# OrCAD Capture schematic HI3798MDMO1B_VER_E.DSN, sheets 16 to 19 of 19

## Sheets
16 SHEET16: size Custom
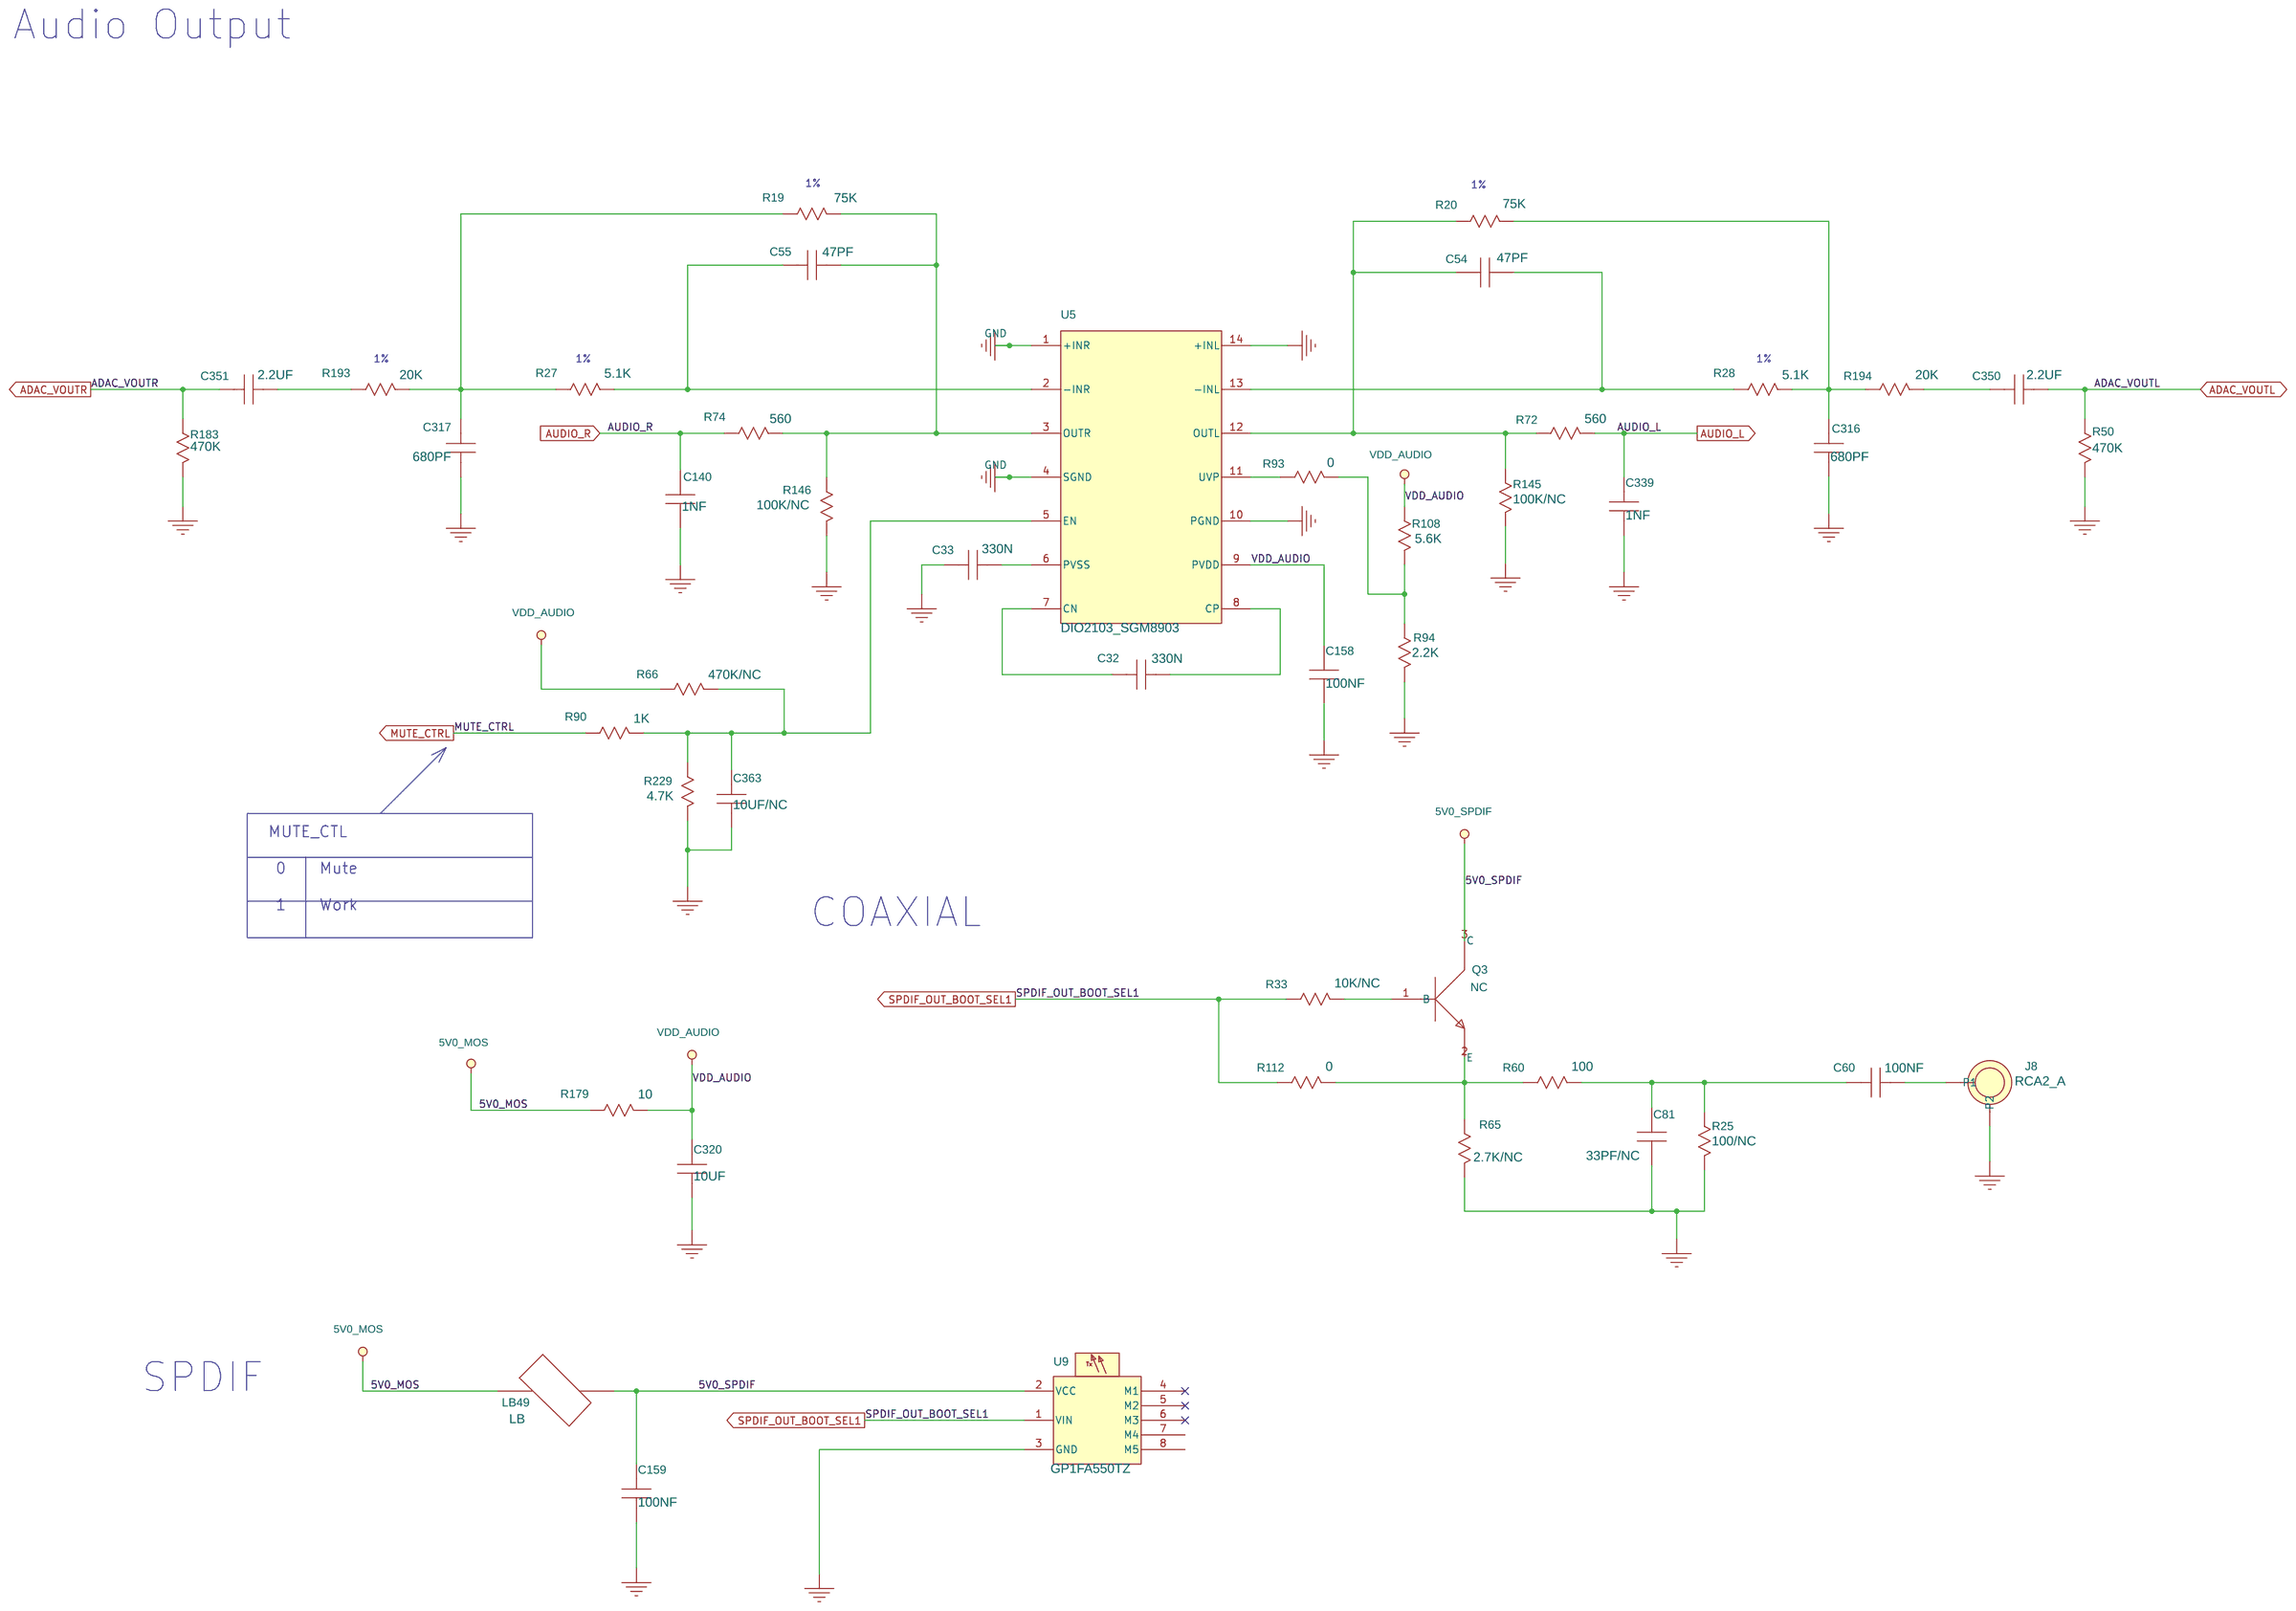
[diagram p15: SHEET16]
17 SHEET17: size Custom
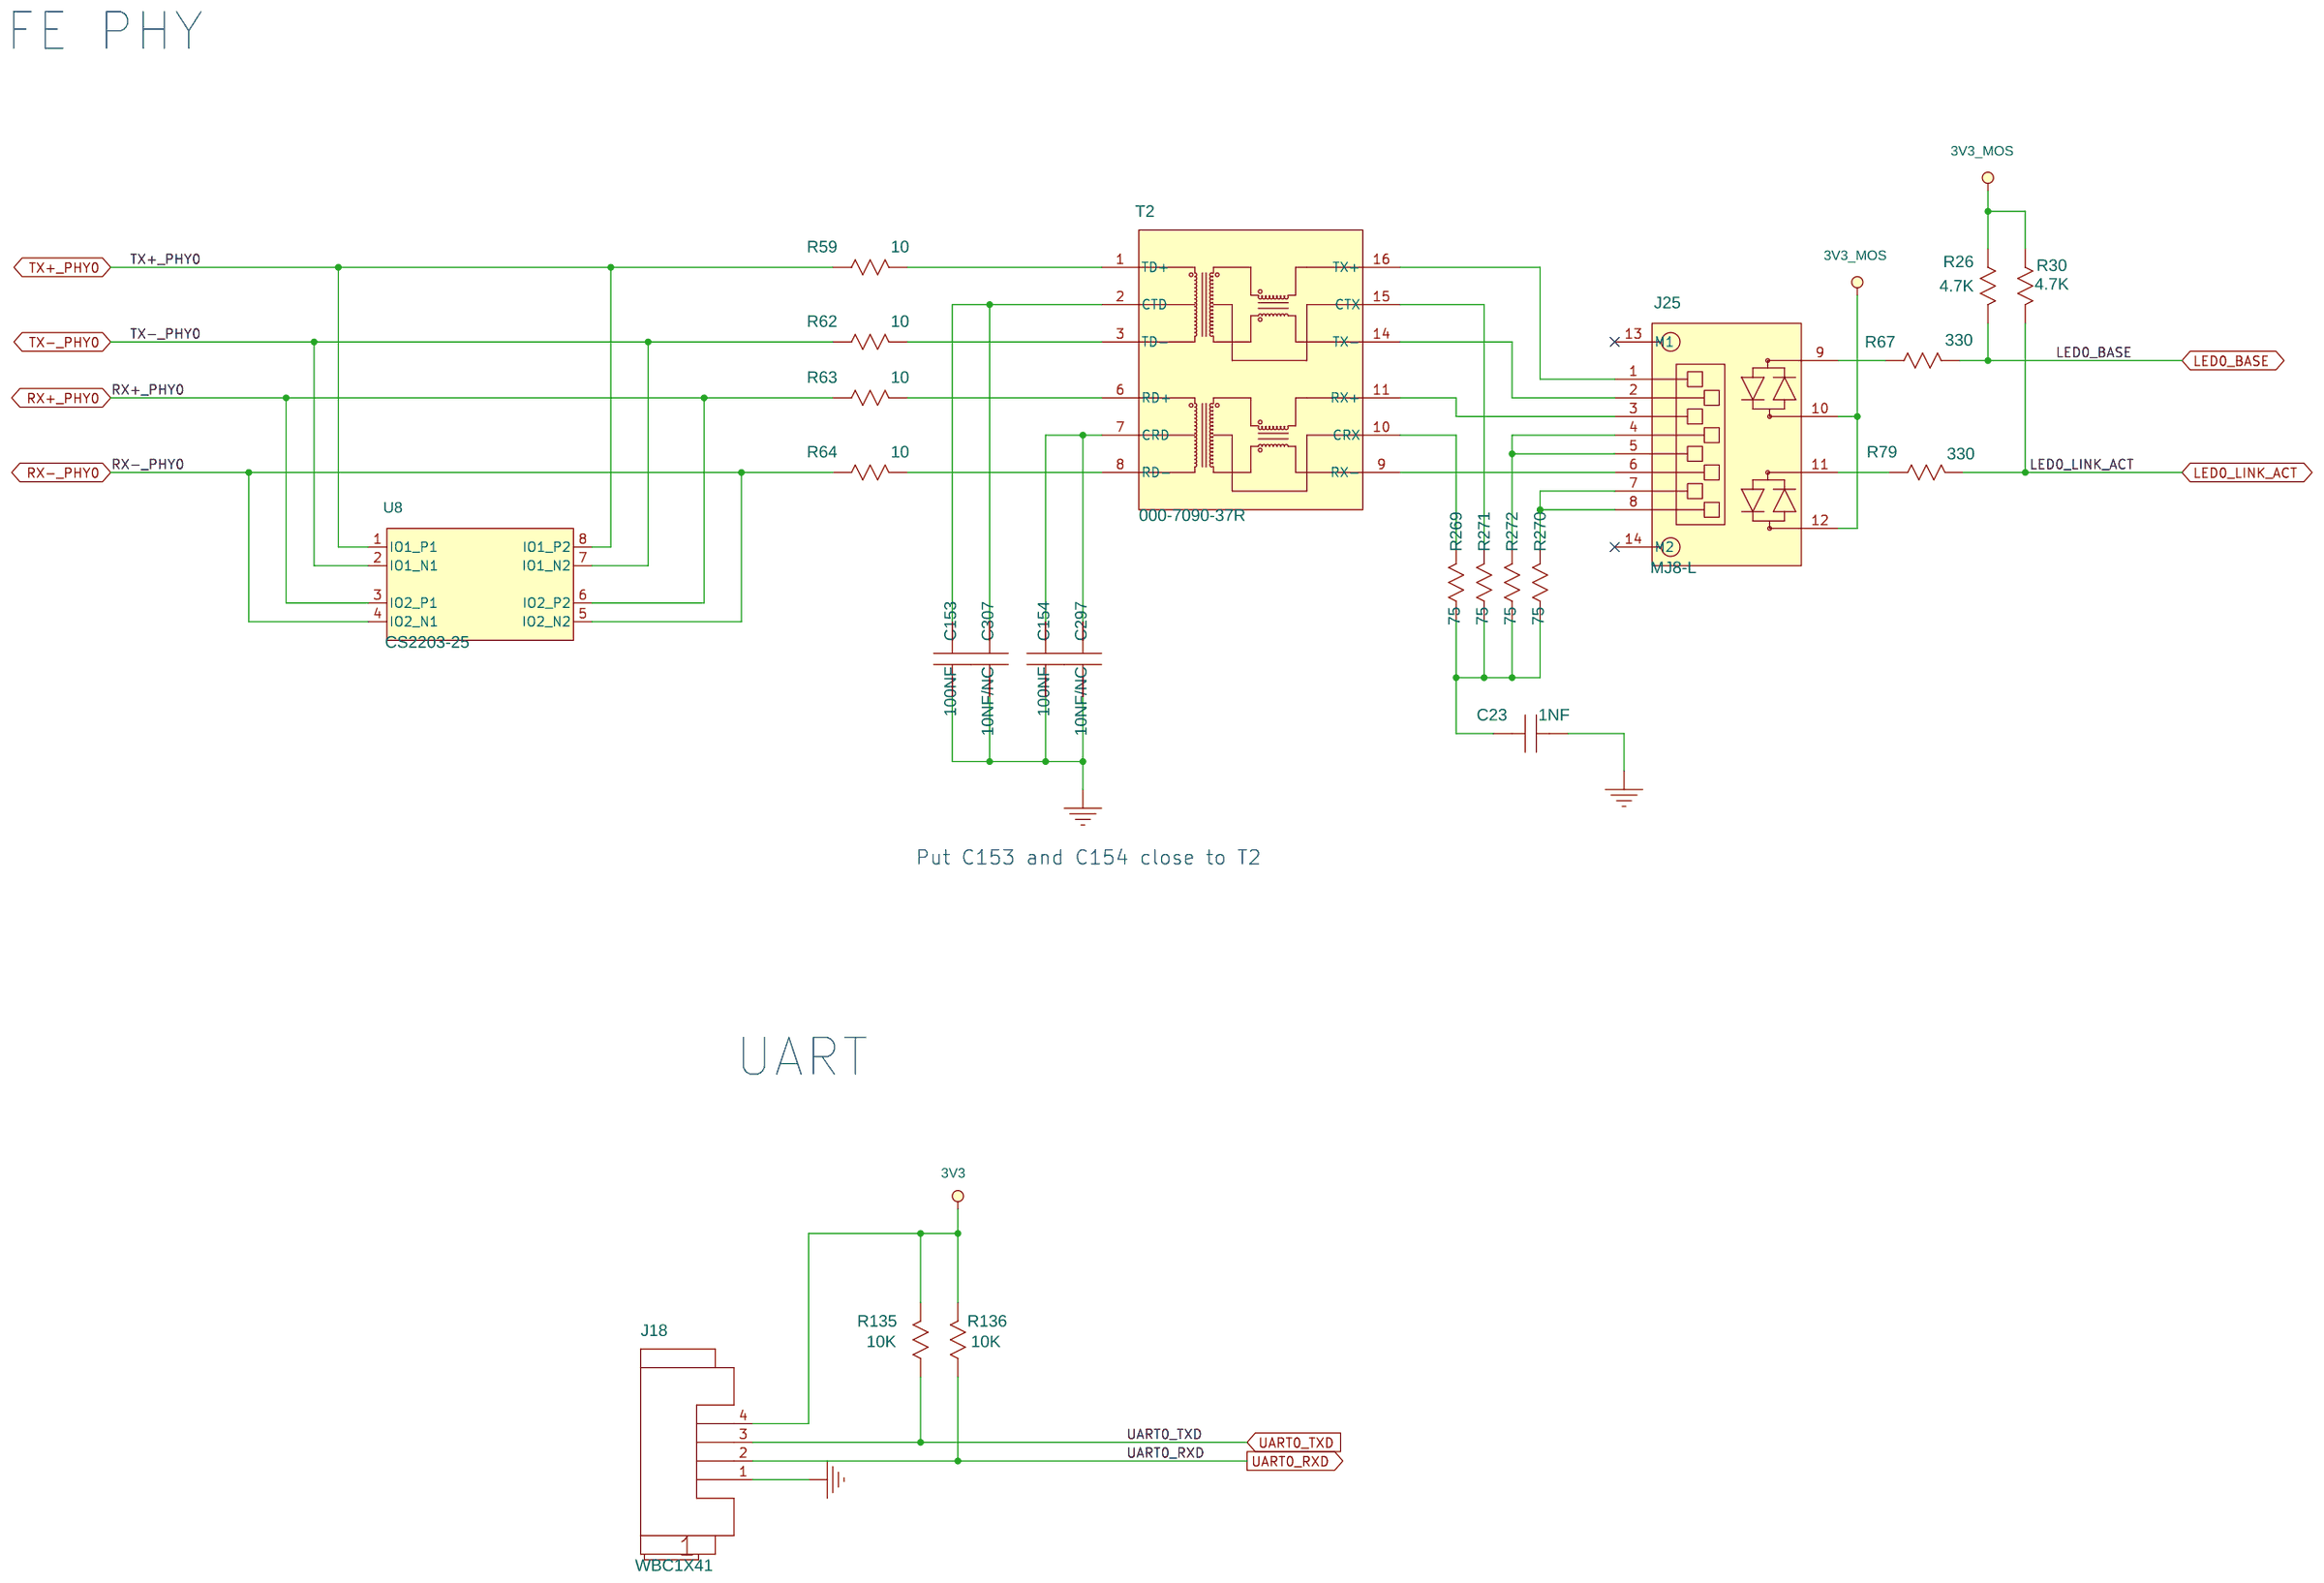
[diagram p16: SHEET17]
18 SHEET18: size A
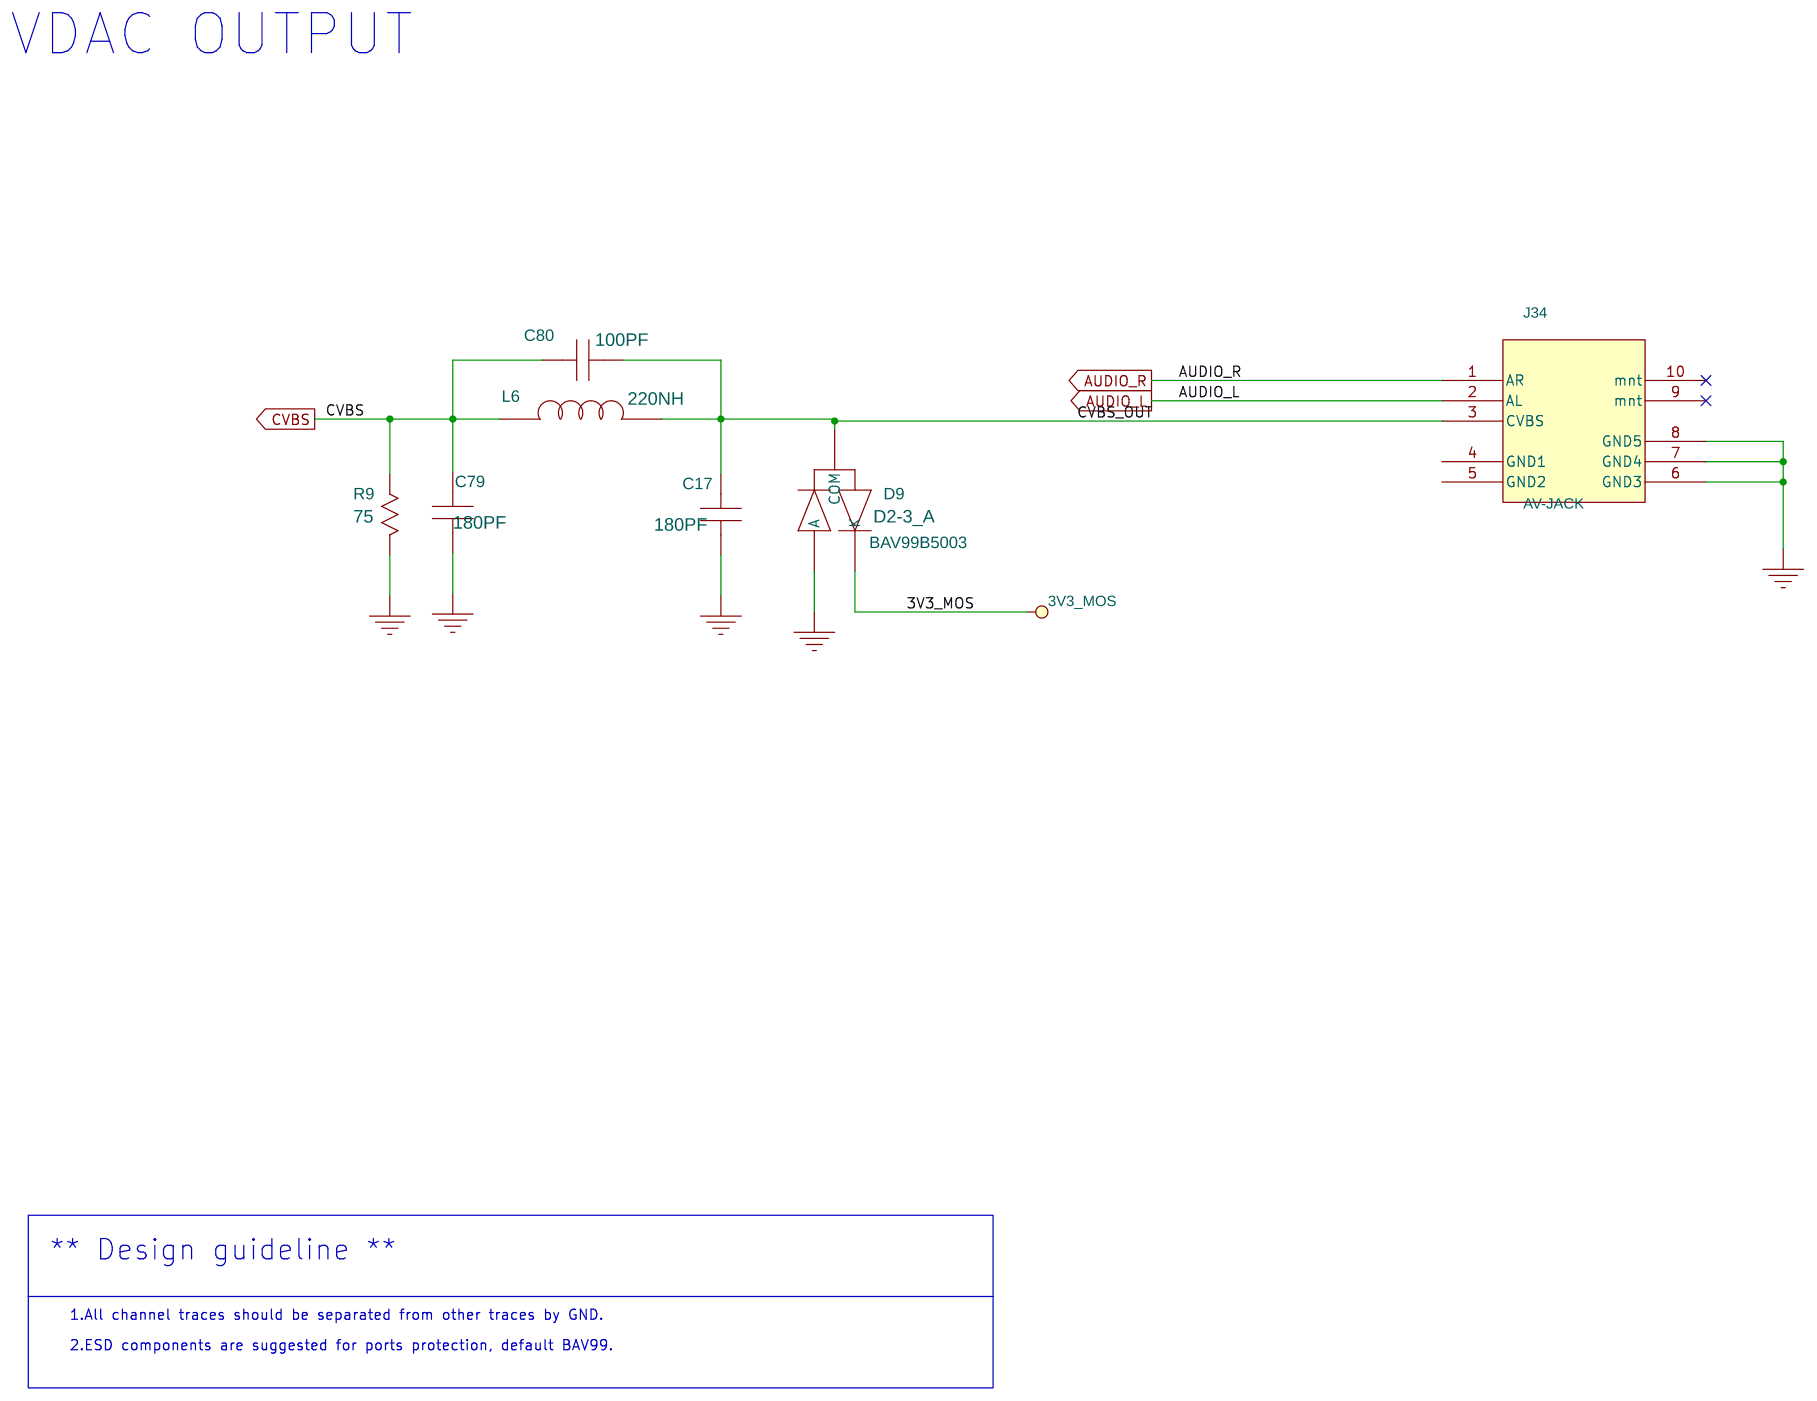
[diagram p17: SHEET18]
19 SHEET19: size Custom
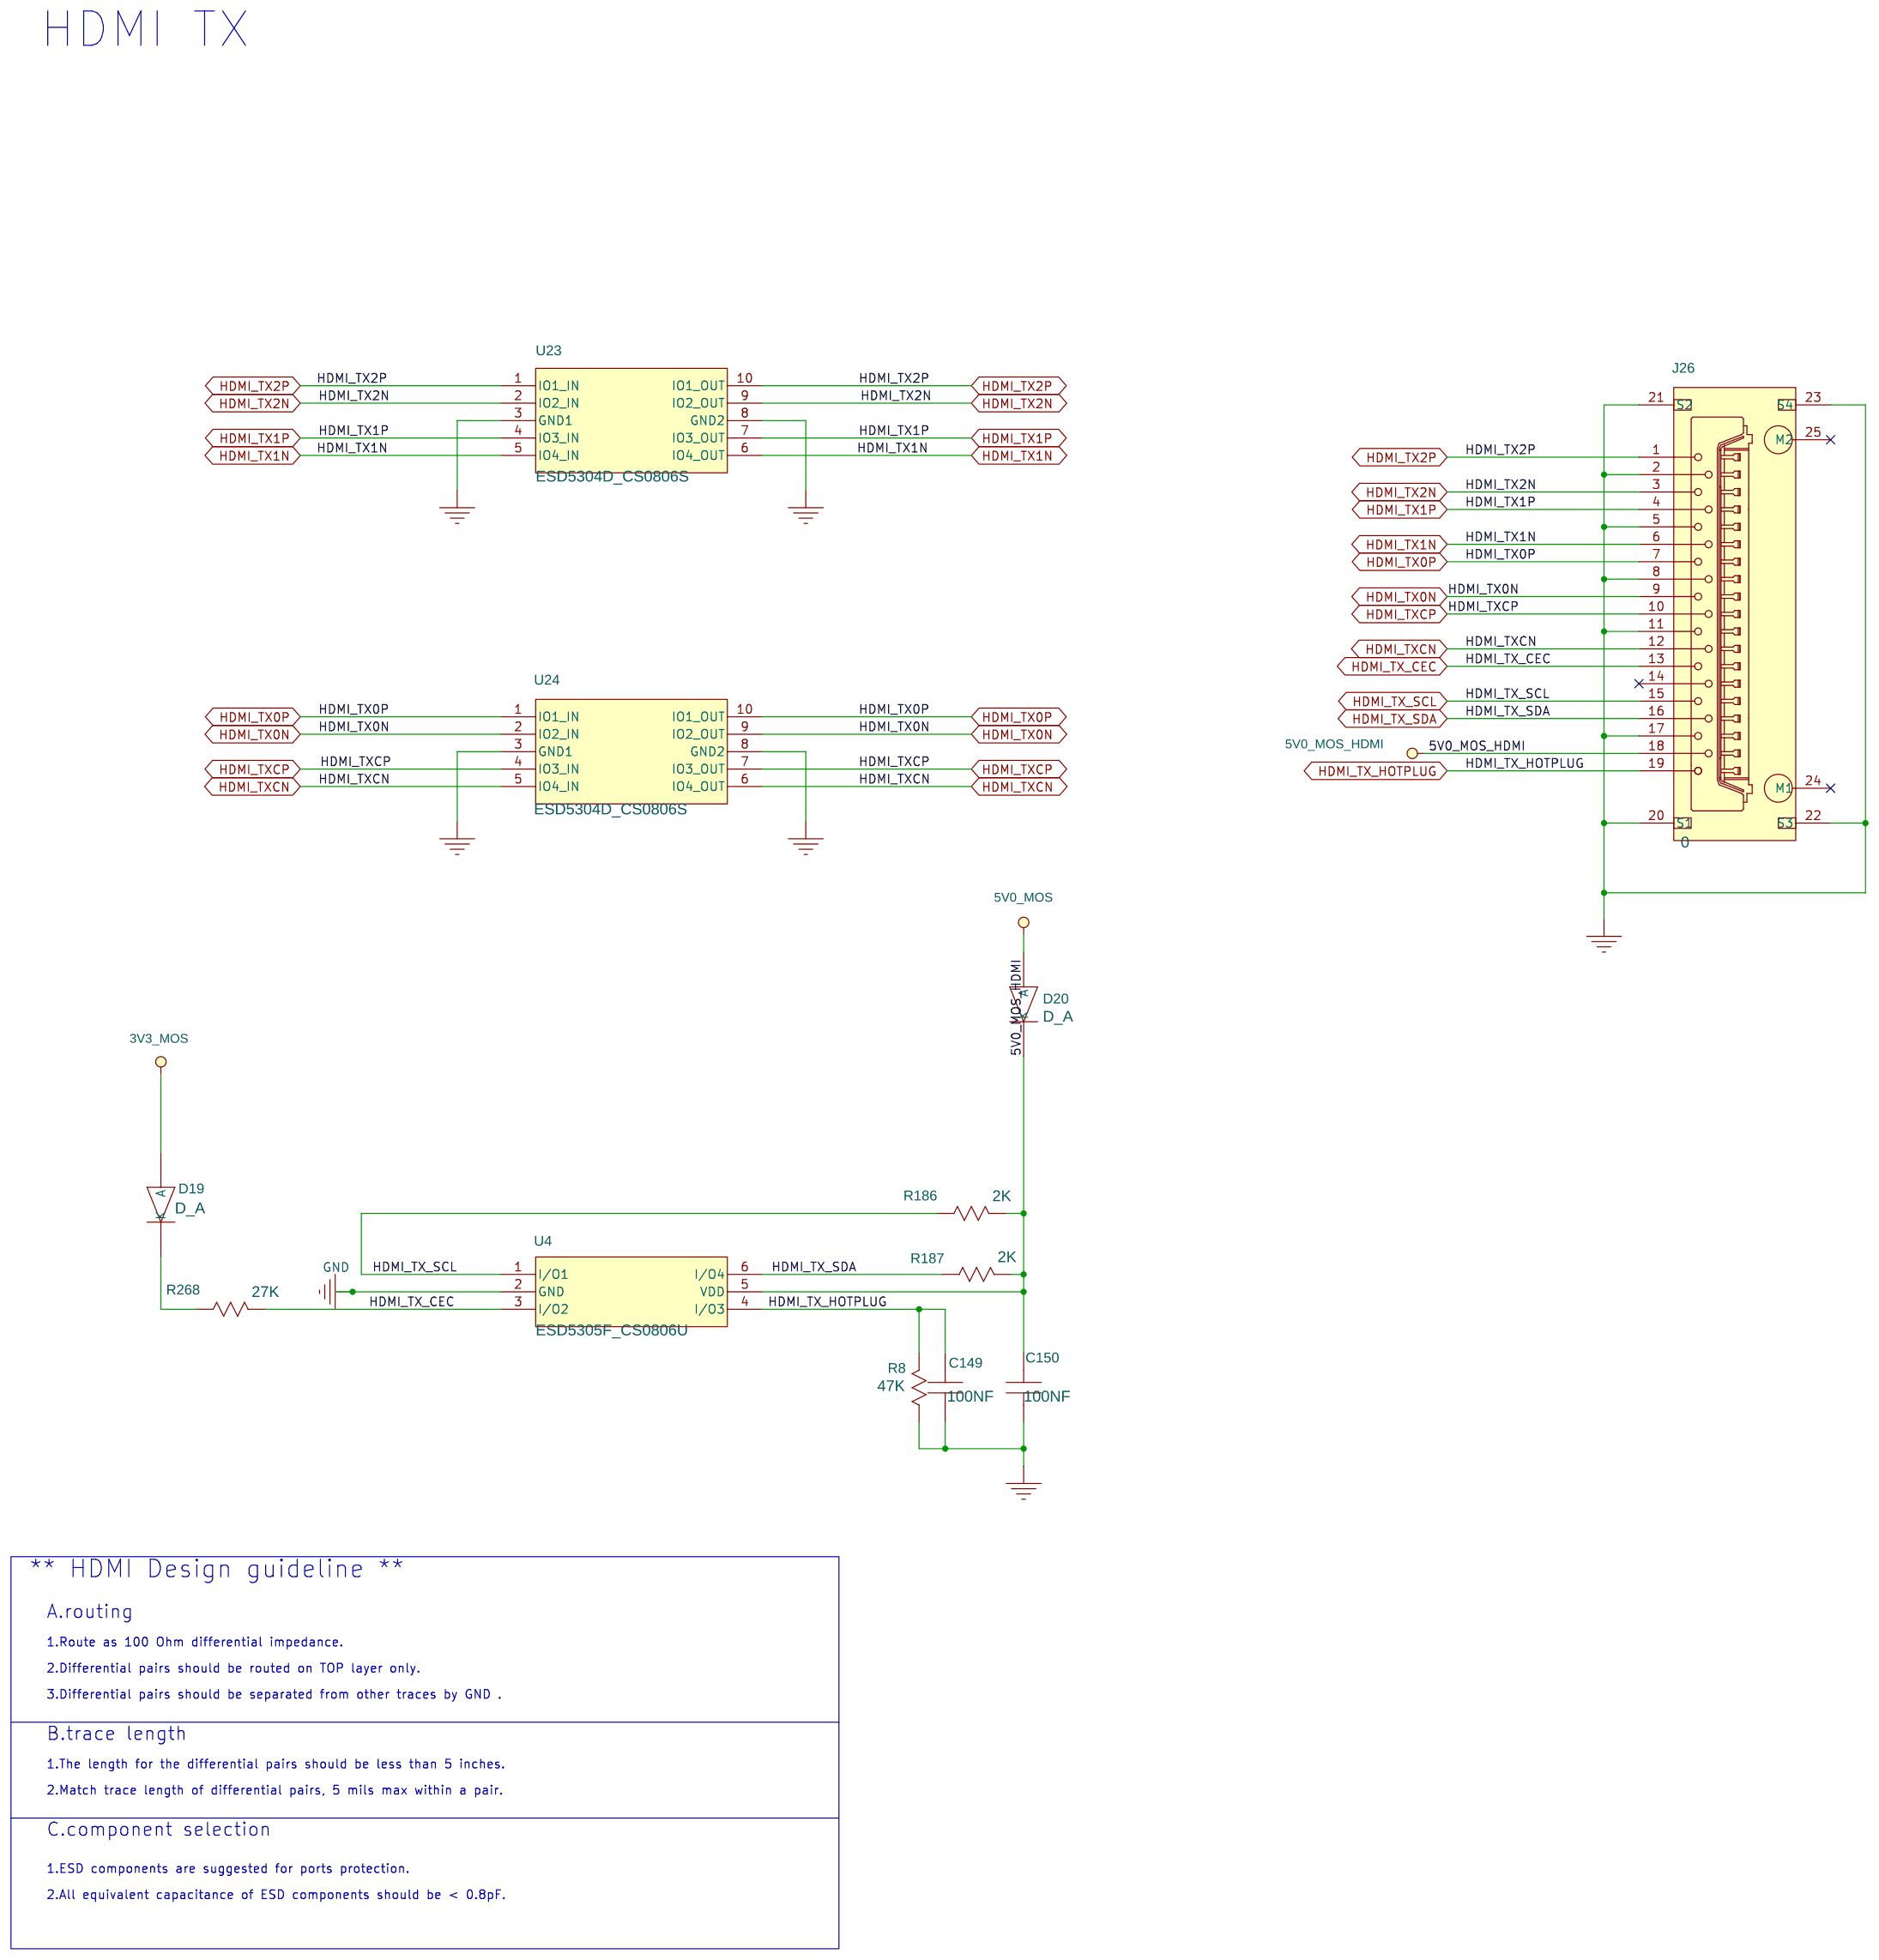
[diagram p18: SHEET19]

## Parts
sheet SHEET16
C32  330N  [HSC0402]
C33  330N  [HSC0402]
C54  47PF  [SC0402]
C55  47PF  [SC0402]
C60  100NF  [SC0402]
C81  33PF/NC  [SC0402]
C140  1NF  [SC0402]
C158  100NF  [SC0402]
C159  100NF  [SC0402]
C316  680PF  [SC0402]
C317  680PF  [SC0402]
C320  10UF  [SC0603]
C339  1NF  [SC0402]
C350  2.2UF  [SC0603]
C351  2.2UF  [SC0603]
C363  10UF/NC  [SC0603]
J8  RCA2_A  [VAF2]
LB49  LB  [SL0805]
Q3  NC  [SOT23]
R19  75K  [SR0603]
R20  75K  [SR0603]
R25  100/NC  [SR0402]
R27  5.1K  [SR0603]
R28  5.1K  [SR0603]
R33  10K/NC  [SR0402]
R50  470K  [SR0402]
R60  100  [SR0402]
R65  2.7K/NC  [SR0603]
R66  470K/NC  [SR0402]
R72  560  [HSR0402]
R74  560  [HSR0402]
R90  1K  [SR0402]
R93  0  [SR0402]
R94  2.2K  [SR0402]
R108  5.6K  [SR0402]
R112  0  [SR0402]
R145  100K/NC  [SR0402]
R146  100K/NC  [SR0402]
R179  10  [SR0603]
R183  470K  [SR0402]
R193  20K  [SR0402]
R194  20K  [SR0402]
R229  4.7K  [SR0402]
U5  DIO2103_SGM8903  [SGM8903]
U9  GP1FA550TZ  [LASER3-1214D]
sheet SHEET17
C23  1NF  [SC1206]
C153  100NF  [SC0402]
C154  100NF  [SC0402]
C297  10NF/NC  [SC0402]
C307  10NF/NC  [SC0402]
J18  WBC1X41  [WBC0104-49T]
J25  MJ8-L  [MJ8-RLY]
R26  4.7K  [SR0402]
R30  4.7K  [SR0402]
R59  10  [SR0402]
R62  10  [SR0402]
R63  10  [SR0402]
R64  10  [SR0402]
R67  330  [SR0402]
R79  330  [SR0402]
R135  10K  [SR0402]
R136  10K  [SR0402]
R269  75  [SR0805]
R270  75  [SR0805]
R271  75  [SR0805]
R272  75  [SR0805]
T2  000-7090-37R  [STFM16-50-285]
U8  CS2203-25  [RN8-0402]
sheet SHEET18
C17  180PF  [SC0402]
C79  180PF  [SC0402]
C80  100PF  [SC0402]
D9  D2-3_A  [SOT23]
J34  AV-JACK  [AV3-8-5-1]
L6  220NH  [SL0402]
R9  75  [SR0402]
sheet SHEET19
C149  100NF  [SC0402]
C150  100NF  [SC0402]
D19  D_A  [HSOD323A]
D20  D_A  [HSOD323A]
J26  0  [WBC0119-20R-A]
R8  47K  [SR0402]
R186  2K  [SR0402]
R187  2K  [SR0402]
R268  27K  [SR0402]
U4  ESD5305F_CS0806U  [SOT23A-6L]
U23  ESD5304D_CS0806S  [DFN2510P10E]
U24  ESD5304D_CS0806S  [DFN2510P10E]

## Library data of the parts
C32 C33 = C: %195%%232%%202%%246%: SMD陶瓷电容-6.3V-330NF-+/-10%-X5R-0402-终端专用; %208%%161%%192%%224%%195%%251%%179%%198%: SMD陶瓷电容; CODE: 8070953; COMPONENT_HIGH_MAX: 0.55MM; DEVICE: C1005X5R0J334K
C54 C55 = C: %182%%238%%182%%168%%185%%164%%215%%247%%181%%231%%209%%185%(V): 50; %195%%232%%202%%246%: SMD陶瓷电容-50V-0.047NF-+/-5%-NP0-0402; %208%%161%%192%%224%%195%%251%%179%%198%: SMD陶瓷电容; CODE: 8070549; COMPONENT_HIGH_MAX: 0.55MM; DEVICE: C0402C470J5GAC_7867
C60 C153 C154 C158 C159 = C: %182%%238%%182%%168%%185%%164%%215%%247%%181%%231%%209%%185%(V): 16; %195%%232%%202%%246%: SMD陶瓷电容-16V-100NF-±10%-X7R-0402; %208%%161%%192%%224%%195%%251%%179%%198%: SMD陶瓷电容; CODE: 8070614; COMPONENT_HIGH_MAX: 0.6MM; DEVICE: RMEMK105BJ104KV_FR
C81 = C: %182%%238%%182%%168%%185%%164%%215%%247%%181%%231%%209%%185%(V): 50; %195%%232%%202%%246%: SMD陶瓷电容-50V-0.033NF-+/-5%-NP0-0402-供电专用-08070547拆分-供电专用; %208%%161%%192%%224%%195%%251%%179%%198%: SMD陶瓷电容; CODE: 8070872; COMPONENT_HIGH_MAX: 0.55MM; DEVICE: C1005C0G1H330JT000F
C140 C339 = C: %182%%238%%182%%168%%185%%164%%215%%247%%181%%231%%209%%185%(V): 50; %195%%232%%202%%246%: SMD陶瓷电容-50V-1NF-+/-10%-X7R-0402-BT; %208%%161%%192%%224%%195%%251%%179%%198%: SMD陶瓷电容; CODE: 8070531; COMPONENT_HIGH_MAX: 0.55MM; DEVICE: 04025C102KAT2A
C316 C317 = C: %182%%238%%182%%168%%185%%164%%215%%247%%181%%231%%209%%185%(V): 50; %195%%232%%202%%246%: SMD陶瓷电容-50V-0.68NF-+/-5%-NP0-0402-供电专用-供电专用; %208%%161%%192%%224%%195%%251%%179%%198%: SMD陶瓷电容; CODE: 8070853; COMPONENT_HIGH_MAX: 0.55MM; DEVICE: C0402C681J5GAC7867
C320 C363 = C: %182%%238%%182%%168%%185%%164%%215%%247%%181%%231%%209%%185%(V): 6.3; %195%%232%%202%%246%: SMD陶瓷电容-6.3V-10000NF-+/-20%-X5R-0603-BT,TS16949; %208%%161%%192%%224%%195%%251%%179%%198%: SMD陶瓷电容; CODE: 8070649; COMPONENT_HIGH_MAX: 0.9MM; DEVICE: C1608X5R0J106MT0A0E
C350 C351 = C: %182%%238%%182%%168%%185%%164%%215%%247%%181%%231%%209%%185%(V): 10; %195%%232%%202%%246%: SMD陶瓷电容-10V-2200NF-+/-10%-X5R-0603; %208%%161%%192%%224%%195%%251%%179%%198%: SMD陶瓷电容; CODE: 8070573; COMPONENT_HIGH_MAX: 0.9MM; DEVICE: GRM188R61A225KE34D
J8 = RCA2_A: %195%%232%%202%%246%: 音视频连接器-RCA莲花插座-2PIN-弯母-PCB焊接型-红色; CODE: 14160120; COMPONENT_HIGH_MAX: 13.5MM; DEVICE: SCP624UNS2
LB49 = LB_v2: %195%%232%%202%%246%: EMI磁珠-220OHM-0.05OHM-2A-0805; %208%%161%%192%%224%%195%%251%%179%%198%: EMI磁珠; CODE: 10070012; COMPONENT_HIGH_MAX: 1.05MM; DEVICE: MGLB2012_220T_LF
Q3 = NPN-BEC: %195%%232%%202%%246%: 三极管-NPN-45V-100MA-225MW-200MV@100MA-SOT-23-180@2MA; %208%%161%%192%%224%%195%%251%%179%%198%: 三极管; CODE: 15050206; COMPONENT_HIGH_MAX: 1.26MM; DEVICE: BC847AE6327
R19 R20 = R: %182%%238%%182%%168%%185%%166%%194%%202%(W): 0.1; %195%%232%%202%%246%: 片式厚膜电阻器-0.1W-75000OHM-+/-1% -0603; %208%%161%%192%%224%%195%%251%%179%%198%: 片式厚膜电阻器; %215%%232%%214%%181%%212%%202%%208%%237%%198%%171%%178%%238%: +/-1%; CODE: 7091238; COMPONENT_HIGH_MAX: 0.55MM; DEVICE: RK73H1JTTD7502F
R25 R33 R60 R65 R112 = R: %195%%232%%202%%246%: 片式厚膜电阻器-0.0625W-100OHM-±5%-0402; CODE: 7090807; COMPONENT_HIGH_MAX: 0.4MM; DEVICE: RC0402JR_07100R
R27 R28 = R: %182%%238%%182%%168%%185%%166%%194%%202%(W): 0.1; %195%%232%%202%%246%: 片式厚膜电阻器-0.1W-5100OHM-+/-1%-0603; %208%%161%%192%%224%%195%%251%%179%%198%: 片式厚膜电阻器; %215%%232%%214%%181%%212%%202%%208%%237%%198%%171%%178%%238%: +/-1%; CODE: 7091295; COMPONENT_HIGH_MAX: 0.55MM; DEVICE: RC0603FR_075K1L
R50 R183 = R: %182%%238%%182%%168%%185%%166%%194%%202%(W): 0.06; %195%%232%%202%%246%: 片式厚膜电阻器-0.0625W-470000OHM-±1%-0402; %208%%161%%192%%224%%195%%251%%179%%198%: 片式厚膜电阻器; %215%%232%%214%%181%%212%%202%%208%%237%%198%%171%%178%%238%: ±1%; CODE: 7090855; COMPONENT_HIGH_MAX: 0.4MM; DEVICE: RK73H1ETTP4703F
R66 = R: %182%%238%%182%%168%%185%%166%%194%%202%(W): 0.06; %195%%232%%202%%246%: 片式厚膜电阻器-0.0625W-470000OHM-+/-1%-0402; %208%%161%%192%%224%%195%%251%%179%%198%: 片式厚膜电阻器; %215%%232%%214%%181%%212%%202%%208%%237%%198%%171%%178%%238%: +/-1%; CODE: 7090855; COMPONENT_HIGH_MAX: 0.4MM; DEVICE: RK73H1ETTP4703F
R72 R74 = R: %195%%232%%202%%246%: 片式厚膜电阻器-0.0625W-560OHM-+/-5%-0402-终端专用-终端专用; %208%%161%%192%%224%%195%%251%%179%%198%: 片式厚膜电阻器; CODE: 7091285; COMPONENT_HIGH_MAX: 0.4MM; DEVICE: RC0402JR_07560RL
R90 = R: %182%%238%%182%%168%%185%%166%%194%%202%(W): 0.06; %195%%232%%202%%246%: 片式厚膜电阻器-0.0625W-1000OHM-±5%-0402; %208%%161%%192%%224%%195%%251%%179%%198%: 片式厚膜电阻器; %215%%232%%214%%181%%212%%202%%208%%237%%198%%171%%178%%238%: ±5%; CODE: 7090809; COMPONENT_HIGH_MAX: 0.4MM; DEVICE: RC0402JR_071KL
R8 R93 = R: %182%%238%%182%%168%%185%%166%%194%%202%(W): 0.06; %195%%232%%202%%246%: 片式厚膜电阻器-0.0625W-47000OHM-+/-5%-0402-ELOM; %208%%161%%192%%224%%195%%251%%179%%198%: 片式厚膜电阻器; %215%%232%%214%%181%%212%%202%%208%%237%%198%%171%%178%%238%: +/-5%; CODE: 7090819; DEVICE: RC0402JR_0747K
R94 = R: %182%%238%%182%%168%%185%%166%%194%%202%(W): 0.06; %195%%232%%202%%246%: 片式厚膜电阻器-0.0625W-2200OHM-+/-1%-0402--供电专用-07090810-供电专用; %208%%161%%192%%224%%195%%251%%179%%198%: 片式厚膜电阻器; %215%%232%%214%%181%%212%%202%%208%%237%%198%%171%%178%%238%: +/-1%; CODE: 7091537; COMPONENT_HIGH_MAX: 0.4MM; DEVICE: RC0402FR_072K2L2
R108 = R: %182%%238%%182%%168%%185%%166%%194%%202%(W): 0.06; %195%%232%%202%%246%: 片式厚膜电阻器-0.0625W-5600OHM-+/-1%-0402-BT; %208%%161%%192%%224%%195%%251%%179%%198%: 片式厚膜电阻器; %215%%232%%214%%181%%212%%202%%208%%237%%198%%171%%178%%238%: +/-1%; CODE: 7091275; COMPONENT_HIGH_MAX: 0.4MM; DEVICE: RK73H1ETTP5601F
R145 R146 = R: %182%%238%%182%%168%%185%%166%%194%%202%(W): 0.06; %195%%232%%202%%246%: 片式厚膜电阻器-0.0625W-100000OHM-+/-5%-0402-BT; %208%%161%%192%%224%%195%%251%%179%%198%: 片式厚膜电阻器; %215%%232%%214%%181%%212%%202%%208%%237%%198%%171%%178%%238%: +/-5%; CODE: 7090831; COMPONENT_HIGH_MAX: 0.4MM; DEVICE: RK73B1ELTP104J
R179 = R: %182%%238%%182%%168%%185%%166%%194%%202%(W): 0.1; %195%%232%%202%%246%: 片式厚膜电阻器-0.1W-10OHM-+/-5%-0603-TS16949; %208%%161%%192%%224%%195%%251%%179%%198%: 片式厚膜电阻器; %215%%232%%214%%181%%212%%202%%208%%237%%198%%171%%178%%238%: +/-5%; CODE: 7090264; COMPONENT_HIGH_MAX: 0.55MM; DEVICE: RC0603JR_0710R
R193 R194 = R: %182%%238%%182%%168%%185%%166%%194%%202%(W): 0.06; %195%%232%%202%%246%: 片式厚膜电阻器-0.0625W-20000OHM-+/-1%-0402-TS16949; %208%%161%%192%%224%%195%%251%%179%%198%: 片式厚膜电阻器; %215%%232%%214%%181%%212%%202%%208%%237%%198%%171%%178%%238%: +/-1%; CODE: 7091374; COMPONENT_HIGH_MAX: 0.4MM; DEVICE: RC_02W2002FT
R229 = R: %182%%238%%182%%168%%185%%166%%194%%202%(W): 0.06; %195%%232%%202%%246%: 片式厚膜电阻器-0.0625W-4700OHM-+/-5%-0402-BT; %208%%161%%192%%224%%195%%251%%179%%198%: 片式厚膜电阻器; %215%%232%%214%%181%%212%%202%%208%%237%%198%%171%%178%%238%: +/-5%; CODE: 7090793; COMPONENT_HIGH_MAX: 0.4MM; DEVICE: RK73B1ELTP472J
U5 = SGM8903
U9 = GP1FA550TZ_1: %195%%232%%202%%246%: 光电器件-数字音频光纤接头-660NM; %208%%161%%192%%224%%195%%251%%179%%198%: 光电器件; CODE: 15020122; COMPONENT_HIGH_MAX: 19.1MM; DEVICE: GP1FAV50TK0F
C23 = C: %182%%238%%182%%168%%185%%164%%215%%247%%181%%231%%209%%185%(V): 2000; %195%%232%%202%%246%: SMD陶瓷电容-2000V-1NF-+/-20%-X7R-1206; %208%%161%%192%%224%%195%%251%%179%%198%: SMD陶瓷电容; CODE: 8070439; COMPONENT_HIGH_MAX: 1.52MM; DEVICE: 1206GC102MAT1A
C297 C307 = C: %182%%238%%182%%168%%185%%164%%215%%247%%181%%231%%209%%185%(V): 16; %195%%232%%202%%246%: SMD陶瓷电容-16V-10NF-+/-10%-X7R-0402-BT,TS16949; %208%%161%%192%%224%%195%%251%%179%%198%: SMD陶瓷电容; CODE: 8070449; COMPONENT_HIGH_MAX: 0.55MM; DEVICE: GRM155R71C103KA01D
J18 = WBC1X41: %195%%232%%202%%246%: 普通插座-4PIN-单排-直式-1.25MM-2MM-THT-1A; %208%%161%%192%%224%%195%%251%%179%%198%: 普通插座; CODE: 14100167; COMPONENT_HIGH_MAX: 4.2MM; DEVICE: SDW12501_4A_HW
J25 = MJ8-L: %195%%232%%202%%246%: 网口连接器-单排-单端口-8PIN-8BIT-非屏蔽-模型插座/侧面插入型-引脚长2.54MM-带固定脚/带灯; %208%%161%%192%%224%%195%%251%%179%%198%: 网口连接器; COMPONENT_HIGH_MAX: 13.2MM; DEVICE: 406533_1
R26 R30 = R: %182%%238%%182%%168%%185%%166%%194%%202%(W): 0.06; %195%%232%%202%%246%: 片式厚膜电阻器-0.0625W-4700OHM-+/-5%-0402; %208%%161%%192%%224%%195%%251%%179%%198%: 片式厚膜电阻器; %215%%232%%214%%181%%212%%202%%208%%237%%198%%171%%178%%238%: +/-5%; CODE: 7090793; COMPONENT_HIGH_MAX: 0.4MM; DEVICE: RK73B1ELTP472J
R59 R62-R64 R67 R79 = R: %182%%238%%182%%168%%185%%166%%194%%202%(W): 0.06; %195%%232%%202%%246%: 片式厚膜电阻器-0.0625W-330OHM-+/-1%-0402-BT; %208%%161%%192%%224%%195%%251%%179%%198%: 片式厚膜电阻器; %215%%232%%214%%181%%212%%202%%208%%237%%198%%171%%178%%238%: +/-1%; CODE: 7091333; COMPONENT_HIGH_MAX: 0.4MM; DEVICE: RC_02W3300FT
R135 R136 = R: %182%%238%%182%%168%%185%%166%%194%%202%(W): 0.06; %195%%232%%202%%246%: 片式厚膜电阻器-0.0625W-10000OHM-±5%-0402; %208%%161%%192%%224%%195%%251%%179%%198%: 片式厚膜电阻器; %215%%232%%214%%181%%212%%202%%208%%237%%198%%171%%178%%238%: ±5%; CODE: 7090815; COMPONENT_HIGH_MAX: 0.4MM; DEVICE: RC_02W103JT
R269-R272 = R: %182%%238%%182%%168%%185%%166%%194%%202%(W): 0.13; %195%%232%%202%%246%: 片式厚膜电阻器-0.125W-75OHM-±1%-0805; %208%%161%%192%%224%%195%%251%%179%%198%: 片式厚膜电阻器; %215%%232%%214%%181%%212%%202%%208%%237%%198%%171%%178%%238%: ±1%; CODE: 7090362; DEVICE: RC0805FR_0775R
T2 = 000-7090-37R: %195%%232%%202%%246%: LAN变压器-1CT:1CT-0.35MH-0UH-1路-2变压器-100BASE-T接口模块-SMT; %208%%161%%192%%224%%195%%251%%179%%198%: LAN变压器; CODE: 9050085; COMPONENT_HIGH_MAX: 6.2MM; DEVICE: H1102T
U8 = CS2203-25_1
C17 C79 = C: %182%%238%%182%%168%%185%%164%%215%%247%%181%%231%%209%%185%(V): 50; %195%%232%%202%%246%: SMD陶瓷电容-50V-0.18NF-+/-5%-NPO-0402; %208%%161%%192%%224%%195%%251%%179%%198%: SMD陶瓷电容; CODE: 8070637; COMPONENT_HIGH_MAX: 0.55MM; DEVICE: CC0402JRNPO9BB181
C80 = C: %182%%238%%182%%168%%185%%164%%215%%247%%181%%231%%209%%185%(V): 50; %195%%232%%202%%246%: SMD陶瓷电容-50V-0.1NF-±5%-NPO-0402; %208%%161%%192%%224%%195%%251%%179%%198%: SMD陶瓷电容; CODE: 8070450; COMPONENT_HIGH_MAX: 0.55MM; DEVICE: 04025A101JAT2A
D9 = D2-3_A: %195%%232%%202%%246%: 开关二极管-70V-200MA-1.25V-6NS-串联-SOT-23-2 FIT; %208%%161%%192%%224%%195%%251%%179%%198%: 开关二极管; CODE: 15010042; COMPONENT_HIGH_MAX: 1.26MM; DEVICE: BAV99B5003
J34 = AV-JACK1_0
L6 = L: %195%%232%%202%%246%: 贴片电感器-0.22UH-+/-5%-3.77OHM-0.3A-0402; %208%%161%%192%%224%%195%%251%%179%%198%: 贴片电感器; CODE: 10031264; COMPONENT_HIGH_MAX: 0.55MM; DEVICE: LGHK1005R22J_T
R9 = R: %182%%238%%182%%168%%185%%166%%194%%202%(W): 0.06; %195%%232%%202%%246%: 片式厚膜电阻器-0.0625W-75OHM-+/-1%-0402; %208%%161%%192%%224%%195%%251%%179%%198%: 片式厚膜电阻器; %215%%232%%214%%181%%212%%202%%208%%237%%198%%171%%178%%238%: +/-1%; CODE: 7091321; COMPONENT_HIGH_MAX: 0.4MM; DEVICE: RC_02W750FT
C149 C150 = C: %182%%238%%182%%168%%185%%164%%215%%247%%181%%231%%209%%185%(V): 16; %195%%232%%202%%246%: SMD陶瓷电容-16V-100NF-+/-10%-X7R-0402-BT; %208%%161%%192%%224%%195%%251%%179%%198%: SMD陶瓷电容; CODE: 8070614; COMPONENT_HIGH_MAX: 0.6MM; DEVICE: RMEMK105BJ104KV_FR
D19 D20 = D_A: %195%%232%%202%%246%: 肖特基二极管-10V-3A-0.24V-SOD323-BT; %208%%161%%192%%224%%195%%251%%179%%198%: 肖特基二极管; CODE: 15010252; COMPONENT_HIGH_MAX: 1.1MM; DEVICE: BAT60BE6327
J26 = WBC1X19S4M2: %195%%232%%202%%246%: IO连接器-HDMI 母座-19PIN-弯式-SMT带DIP脚-终端专用; %208%%161%%192%%224%%195%%251%%179%%198%: IO连接器; CODE: 14240146; COMPONENT_HIGH_MAX: 6.38MM; DEVICE: 1827059_3
R186 R187 = R: %182%%238%%182%%168%%185%%166%%194%%202%(W): 0.06; %195%%232%%202%%246%: 片式厚膜电阻器-0.0625W-2000OHM-+/-1%-0402-BT; %208%%161%%192%%224%%195%%251%%179%%198%: 片式厚膜电阻器; %215%%232%%214%%181%%212%%202%%208%%237%%198%%171%%178%%238%: +/-1%; CODE: 7091354; COMPONENT_HIGH_MAX: 0.4MM; DEVICE: RC_02W2001FT
R268 = R: %182%%238%%182%%168%%185%%166%%194%%202%(W): 0.06; %195%%232%%202%%246%: 片式厚膜电阻器-0.0625W-27000OHM-+/-5%-0402; %208%%161%%192%%224%%195%%251%%179%%198%: 片式厚膜电阻器; %215%%232%%214%%181%%212%%202%%208%%237%%198%%171%%178%%238%: +/-5%; CODE: 7090852; COMPONENT_HIGH_MAX: 0.4MM; DEVICE: RK73B1ETTP273J
U4 = CS0806U
U23 = CS0806S: #: 3
U24 = CS0806S

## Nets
3V3: J18.4 R135.1(A) R136.2(B) ; also on sheet 4 5 6 9 15
3V3_MOS: D9.2(K) D19.2(A) J25.10 J25.12 R26.1(A) R30.1(A) ; also on sheet 5 6 7 8 9 13 14 15
5V0_MOS: D20.2(A) LB49.1 R179.1(A) ; also on sheet 5 14
5V0_MOS_HDMI: C150.1(A) D20.1(K) J26.18 R186.2(B) R187.2(B) U4.5(VDD)
5V0_SPDIF: C159.1(A) LB49.2 Q3.3(C) U9.2(VCC)
GND: C17.2(B) C23.2(B) C33.1(A) C79.2(B) C81.2(B) C140.2(B) C149.2(B) C150.2(B) C153.2(B) C154.2(B) C158.2(B) C159.2(B) C297.2(B) C307.2(B) C316.2(B) C317.2(B) C320.2(B) C339.2(B) C363.2(B) D9.1(A) J8.2(P2) J18.1 J26.2 J26.5 J26.8 J26.11 J26.17 J26.20(S1) J26.21(S2) J26.22(S3) J26.23(S4) J34.6(GND3) J34.7(GND4) J34.8(GND5) R8.1(A) R9.2(B) R25.2(B) R50.2(B) R65.2(B) R94.2(B) R145.2(B) R146.2(B) R183.2(B) R229.2(B) U4.2(GND) U5.1(+INR) U5.4(SGND) U5.10(PGND) U5.14(+INL) U9.3(GND) U23.3(GND1) U23.8(GND2) U24.3(GND1) U24.8(GND2) ; also on sheet 3 4 5 6 7 8 9 10 11 12 13 14 15
VDD_AUDIO: C158.1(A) C320.1(A) R66.2(B) R108.1(A) R179.2(B) U5.9(PVDD)
ADAC_VOUTL: C350.2(B) R50.1(A) ; also on sheet 7
ADAC_VOUTR: C351.1(A) R183.1(A) ; also on sheet 7
AUDIO_L: C339.1(A) J34.2(AL) R72.2(B)
AUDIO_R: C140.1(A) J34.1(AR) R74.1(A)
CVBS: C79.1(A) C80.1(A) L6.1(A) R9.1(A) ; also on sheet 7
CVBS_OUT: C17.1(A) C80.2(B) D9.3(COM) J34.3(CVBS) L6.2(B)
HDMI_TX0N: J26.9 U24.2(IO2_IN) U24.9(IO2_OUT) ; also on sheet 7
HDMI_TX0P: J26.7 U24.1(IO1_IN) U24.10(IO1_OUT) ; also on sheet 7
HDMI_TX1N: J26.6 U23.5(IO4_IN) U23.6(IO4_OUT) ; also on sheet 7
HDMI_TX1P: J26.4 U23.4(IO3_IN) U23.7(IO3_OUT) ; also on sheet 7
HDMI_TX2N: J26.3 U23.2(IO2_IN) U23.9(IO2_OUT) ; also on sheet 7
HDMI_TX2P: J26.1 U23.1(IO1_IN) U23.10(IO1_OUT) ; also on sheet 7
HDMI_TX_CEC: J26.13 R268.2(B) U4.3(I/O2) ; also on sheet 7
HDMI_TX_HOTPLUG: C149.1(A) J26.19 R8.2(B) U4.4(I/O3) ; also on sheet 7
HDMI_TX_SCL: J26.15 R186.1(A) U4.1(I/O1) ; also on sheet 7
HDMI_TX_SDA: J26.16 R187.1(A) U4.6(I/O4) ; also on sheet 7
HDMI_TXCN: J26.12 U24.5(IO4_IN) U24.6(IO4_OUT) ; also on sheet 7
HDMI_TXCP: J26.10 U24.4(IO3_IN) U24.7(IO3_OUT) ; also on sheet 7
LED0_BASE: R26.2(B) R67.2(B) ; also on sheet 6
LED0_LINK_ACT: R30.2(B) R79.2(B) ; also on sheet 6
MUTE_CTRL: R90.1(A) ; also on sheet 7
RX+_PHY0: R63.1(A) U8.3(IO2_P1) U8.6(IO2_P2) ; also on sheet 6
RX-_PHY0: R64.1(A) U8.4(IO2_N1) U8.5(IO2_N2) ; also on sheet 6
SPDIF_OUT_BOOT_SEL1: R33.1(A) R112.1(A) U9.1(VIN) ; also on sheet 6 7
TX+_PHY0: R59.1(A) U8.1(IO1_P1) U8.8(IO1_P2) ; also on sheet 6
TX-_PHY0: R62.1(A) U8.2(IO1_N1) U8.7(IO1_N2) ; also on sheet 6
UART0_RXD: J18.2 R136.1(A) ; also on sheet 7
UART0_TXD: J18.3 R135.2(B) ; also on sheet 7
N00501: D19.1(K) R268.1(A)
N01199: C153.1(A) C307.1(A) T2.2(CTD)
N01209: J25.4 J25.5 R272.2(B)
N01219: J25.2 T2.14(TX-)
N01227: J25.1 T2.16(TX+)
N01235: C23.1(A) R269.1(A) R270.1(A) R271.1(A) R272.1(A)
N01255: J25.3 T2.11(RX+)
N01263: J25.6 T2.9(RX-)
N01267: R269.2(B) T2.10(CRX)
N01273: R271.2(B) T2.15(CTX)
N01279: J25.7 J25.8 R270.2(B)
N01289: J25.11 R79.1(A)
N01293: J25.9 R67.1(A)
N01297: C154.1(A) C297.1(A) T2.7(CRD)
N01928: C60.1(A) C81.1(A) R25.1(A) R60.2(B)
N02044: C363.1(A) R66.1(A) R90.2(B) R229.1(A) U5.5(EN)
N02078: R93.2(B) R94.1(A) R108.2(B)
N02126: C32.2(B) U5.8(CP)
N02134: C33.2(B) U5.6(PVSS)
N02138: C32.1(A) U5.7(CN)
N02154: C54.2(B) R28.1(A) U5.13(-INL)
N02172: C316.1(A) R20.2(B) R28.2(B) R194.1(A)
N02184: C350.1(A) R194.2(B)
N02188: C54.1(A) R20.1(A) R72.1(A) R145.1(A) U5.12(OUTL)
N02214: C55.1(A) R27.2(B) U5.2(-INR)
N02224: C55.2(B) R19.2(B) R74.2(B) R146.1(A) U5.3(OUTR)
N02250: C317.1(A) R19.1(A) R27.1(A) R193.2(B)
N02262: C351.2(B) R193.1(A)
N02266: R93.1(A) U5.11(UVP)
N02270: C60.2(B) J8.1(P1)
N16742628: Q3.1(B) R33.2(B)
N16861567: Q3.2(E) R60.1(A) R65.1(A) R112.2(B)
N16884560: R64.2(B) T2.8(RD-)
N16884562: R63.2(B) T2.6(RD+)
N16884564: R62.2(B) T2.3(TD-)
N16884566: R59.2(B) T2.1(TD+)

Not connected (* = marked no-connect by the designer): J25 13(M1)* 14(M2)*; J26 14* 24(M1)* 25(M2)*; J34 4(GND1) 5(GND2) 9(mnt)* 10(mnt)*; U9 4(M1)* 5(M2)* 6(M3)* 7(M4) 8(M5)

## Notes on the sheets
sheet 16
- Audio Output
- 1%
- 1%
- 1%
- 1%
- 1%
- MUTE_CTL
- 0
- Mute
- COAXIAL
- 1
- Work
- SPDIF
sheet 17
- FE PHY
- Put C153 and C154 close to T2
- UART
sheet 18
- VDAC OUTPUT
- ** Design guideline **
- 1.All channel traces should be separated from other traces by GND.
- 2.ESD components are suggested for ports protection, default BAV99.
sheet 19
- HDMI TX
- ** HDMI Design guideline **
- A.routing
- 1.Route as 100 Ohm differential impedance.
- 2.Differential pairs should be routed on TOP layer only.
- 3.Differential pairs should be separated from other traces by GND .
- B.trace length
- 1.The length for the differential pairs should be less than 5 inches.
- 2.Match trace length of differential pairs, 5 mils max within a pair.
- C.component selection
- 1.ESD components are suggested for ports protection.
- 2.All equivalent capacitance of ESD components should be < 0.8pF.
